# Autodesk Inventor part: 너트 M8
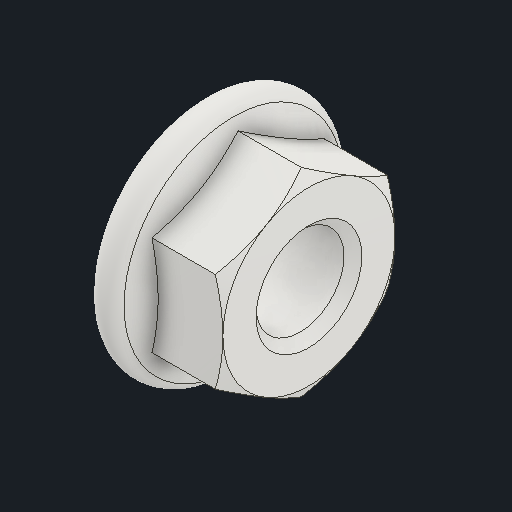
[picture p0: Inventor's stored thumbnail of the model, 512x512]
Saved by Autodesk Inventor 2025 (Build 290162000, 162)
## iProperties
Created: 2025-08
Part Number: 너트 M8
Material: 스테인리스강
Description: 플랜지붙이 6각 너트 - 일반 스레드
Document SubType Name: Modeling
Designer: infra027
Density: 8 g/cm^3
Appearance: 기본값
Author: jhkim
Sending System: Autodesk Inventor 2026
Preprocessor: ST-DEVELOPER v20.1
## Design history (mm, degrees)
feature "Solid1"
node "솔리드1"
